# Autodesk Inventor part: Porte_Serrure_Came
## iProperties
Created: 2009-01
Part Number: Porte_Serrure_Came
Document SubType Name: Modeling
Designer: claivier
Author: claivier
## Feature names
1. Base1
